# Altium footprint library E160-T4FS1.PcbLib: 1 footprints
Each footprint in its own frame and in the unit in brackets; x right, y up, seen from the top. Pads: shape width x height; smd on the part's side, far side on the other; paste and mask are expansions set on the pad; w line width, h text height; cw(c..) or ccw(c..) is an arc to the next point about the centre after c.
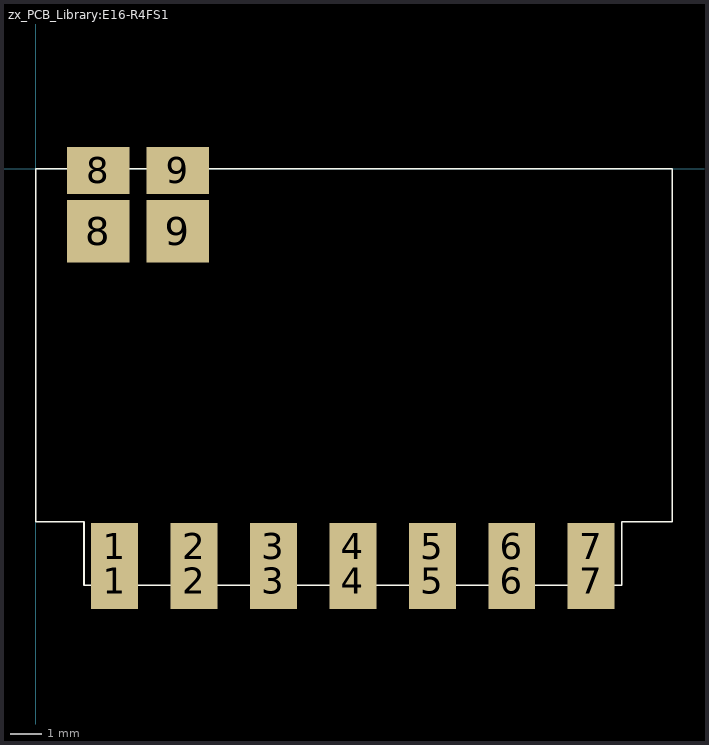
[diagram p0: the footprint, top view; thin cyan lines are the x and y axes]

## zx_PCB_Library:E16-R4FS1 [mm]
pads (18):
  rect 1.5x1.8 smd paste+0 mask+0: 1(2.52,-13.18) 2(5.06,-13.18) 3(7.6,-13.18) 4(10.14,-13.18) 5(12.68,-13.18) 6(15.22,-13.18) 7(17.76,-13.18)
  rect 1.5x1.5 smd paste+0 mask+0: 1(2.52,-12.08) 2(5.06,-12.08) 3(7.6,-12.08) 4(10.14,-12.08) 5(12.68,-12.08) 6(15.22,-12.08) 7(17.76,-12.08)
  rect 2x2 smd paste+0 mask+0: 8(2,-2) 9(4.54,-2)
  rect 2x1.5 smd paste+0 mask+0: 8(2,-0.058) 9(4.54,-0.058)
Top Overlay:
  lines w0.05: 0,-11.3 1.54,-11.3 1.54,-13.33 18.74,-13.33 18.74,-11.3 20.35,-11.3 20.35,0 0,0 0,-11.3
